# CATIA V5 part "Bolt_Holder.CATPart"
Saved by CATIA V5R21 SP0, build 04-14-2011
Part number: Bolt_Holder
Bounding box of the stored display mesh (mm): x -89 to 89, y -7 to 7, z 0 to 2.8
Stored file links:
  C:\Users\Pouria\Desktop\Box\Bolt_Holder.CATPart
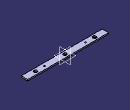
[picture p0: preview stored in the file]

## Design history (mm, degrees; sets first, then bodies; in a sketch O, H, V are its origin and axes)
Body1 (main body)
  Sketch1 on xy-plane, origin (0, 0, 0), H (1, 0, 0), V (0, 1, 0)
    line L1 (89, 7) -> (89, -7)
    line L2 (89, -7) -> (-89, -7)
    line L3 (-89, -7) -> (-89, 7)
    line L4 (-89, 7) -> (89, 7)
    circle A1 centre (45, 0) radius 1.5
    point P5 (45, 0)
    circle A2 centre (-45, 0) radius 1.5
    point P6 (-45, 0)
    point P7 (65, 0)
    point P8 (67.0207, 3.5)
    point P9 (62.9793, 3.5)
    point P10 (60.9585, 0)
    point P11 (62.9793, -3.5)
    point P12 (67.0207, -3.5)
    point P13 (69.0415, 0)
    point P14 (65, 3.5)
    line L5 (67.0207, 3.5) -> (62.9793, 3.5)
    line L6 (62.9793, 3.5) -> (60.9585, 0)
    line L7 (60.9585, 0) -> (62.9793, -3.5)
    line L8 (62.9793, -3.5) -> (67.0207, -3.5)
    line L9 (67.0207, -3.5) -> (69.0415, 0)
    line L10 (69.0415, 0) -> (67.0207, 3.5)
    construction line L11 (65, 0) -> (65, 3.5)
    construction circle A3 centre (65, 0) radius 4.0415
    construction arc A4 centre (67.0207, -3.5) radius 4.0415 from (62.9793, -3.5) to (69.0415, 0) cw
    construction arc A5 centre (62.9793, 3.5) radius 4.0415 from (60.9585, 0) to (67.0207, 3.5) ccw
    point P15 (-65, 0)
    point P16 (-62.9793, 3.5)
    point P17 (-67.0207, 3.5)
    point P18 (-69.0415, 0)
    point P19 (-67.0207, -3.5)
    point P20 (-62.9793, -3.5)
    point P21 (-60.9585, 0)
    point P22 (-65, 3.5)
    line L12 (-62.9793, 3.5) -> (-67.0207, 3.5)
    line L13 (-67.0207, 3.5) -> (-69.0415, 0)
    line L14 (-69.0415, 0) -> (-67.0207, -3.5)
    line L15 (-67.0207, -3.5) -> (-62.9793, -3.5)
    line L16 (-62.9793, -3.5) -> (-60.9585, 0)
    line L17 (-60.9585, 0) -> (-62.9793, 3.5)
    construction line L18 (-65, 0) -> (-65, 3.5)
    construction circle A6 centre (-65, 0) radius 4.0415
    construction arc A7 centre (-62.9793, -3.5) radius 4.0415 from (-67.0207, -3.5) to (-60.9585, 0) cw
    construction arc A8 centre (-67.0207, 3.5) radius 4.0415 from (-69.0415, 0) to (-62.9793, 3.5) ccw
    point P23 (4.0415, 0)
    point P24 (2.0207, 3.5)
    point P25 (-2.0207, 3.5)
    point P26 (-4.0415, 0)
    point P27 (-2.0207, -3.5)
    point P28 (2.0207, -3.5)
    point P29 (3.0311, 1.75)
    line L19 (4.0415, 0) -> (2.0207, 3.5)
    line L20 (2.0207, 3.5) -> (-2.0207, 3.5)
    line L21 (-2.0207, 3.5) -> (-4.0415, 0)
    line L22 (-4.0415, 0) -> (-2.0207, -3.5)
    line L23 (-2.0207, -3.5) -> (2.0207, -3.5)
    line L24 (2.0207, -3.5) -> (4.0415, 0)
    construction line L25 (0, 0) -> (3.0311, 1.75)
    construction circle A9 centre (0, 0) radius 4.0415
    construction arc A10 centre (-2.0207, -3.5) radius 4.0415 from (-4.0415, 0) to (2.0207, -3.5) cw
    construction arc A11 centre (2.0207, 3.5) radius 4.0415 from (-2.0207, 3.5) to (4.0415, 0) ccw
    length L4 = 178
    length L1 = 14
    distance P6 L3 = 44
    distance P5 L1 = 44
    radius A1 = 1.5
    radius A2 = 1.5
    distance L8 L5 = 7
    distance L15 L12 = 7
    distance P7 L1 = 24
    distance P15 L3 = 24
    vertical: L1 V, L3 V, L11 V, L18 V
    horizontal: L2 H, L4 H, L5 H, L12 H, L20 H
    equidistance: L1 L3 O, L2 L4 O
    coincidence: P5 H, P6 H, P7 H, A3 P8, A3 P9, A3 P10, A3 P11, A3 P12, A3 P13, A4 P7, A5 P7, P15 H, A6 P16, A6 P17, A6 P18, A6 P19, A6 P20, A6 P21, A7 P15, A8 P15, A9 P23, A9 P24, A9 P25, A9 P26, A9 P27, A9 P28, A10 O, A11 O, L20 L5
    midpoint: P14 L5, P22 L12, P29 L19
    parallelism: L19 L22
  Pad1: profile Sketch1, direction (0, 0, 1), length 2.8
